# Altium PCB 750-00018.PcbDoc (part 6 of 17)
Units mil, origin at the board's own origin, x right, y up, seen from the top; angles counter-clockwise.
Board outline 7086.64 x 6299.21 mil, 8 copper layers (Top Layer, L2, L3, L4, L5, L6, L7, Bottom Layer), stack 60.6 mil thick; 1356 components, 1054 nets, 4851 pads, 4296 vias.
Unrouted connection lines stored in the file: 12.
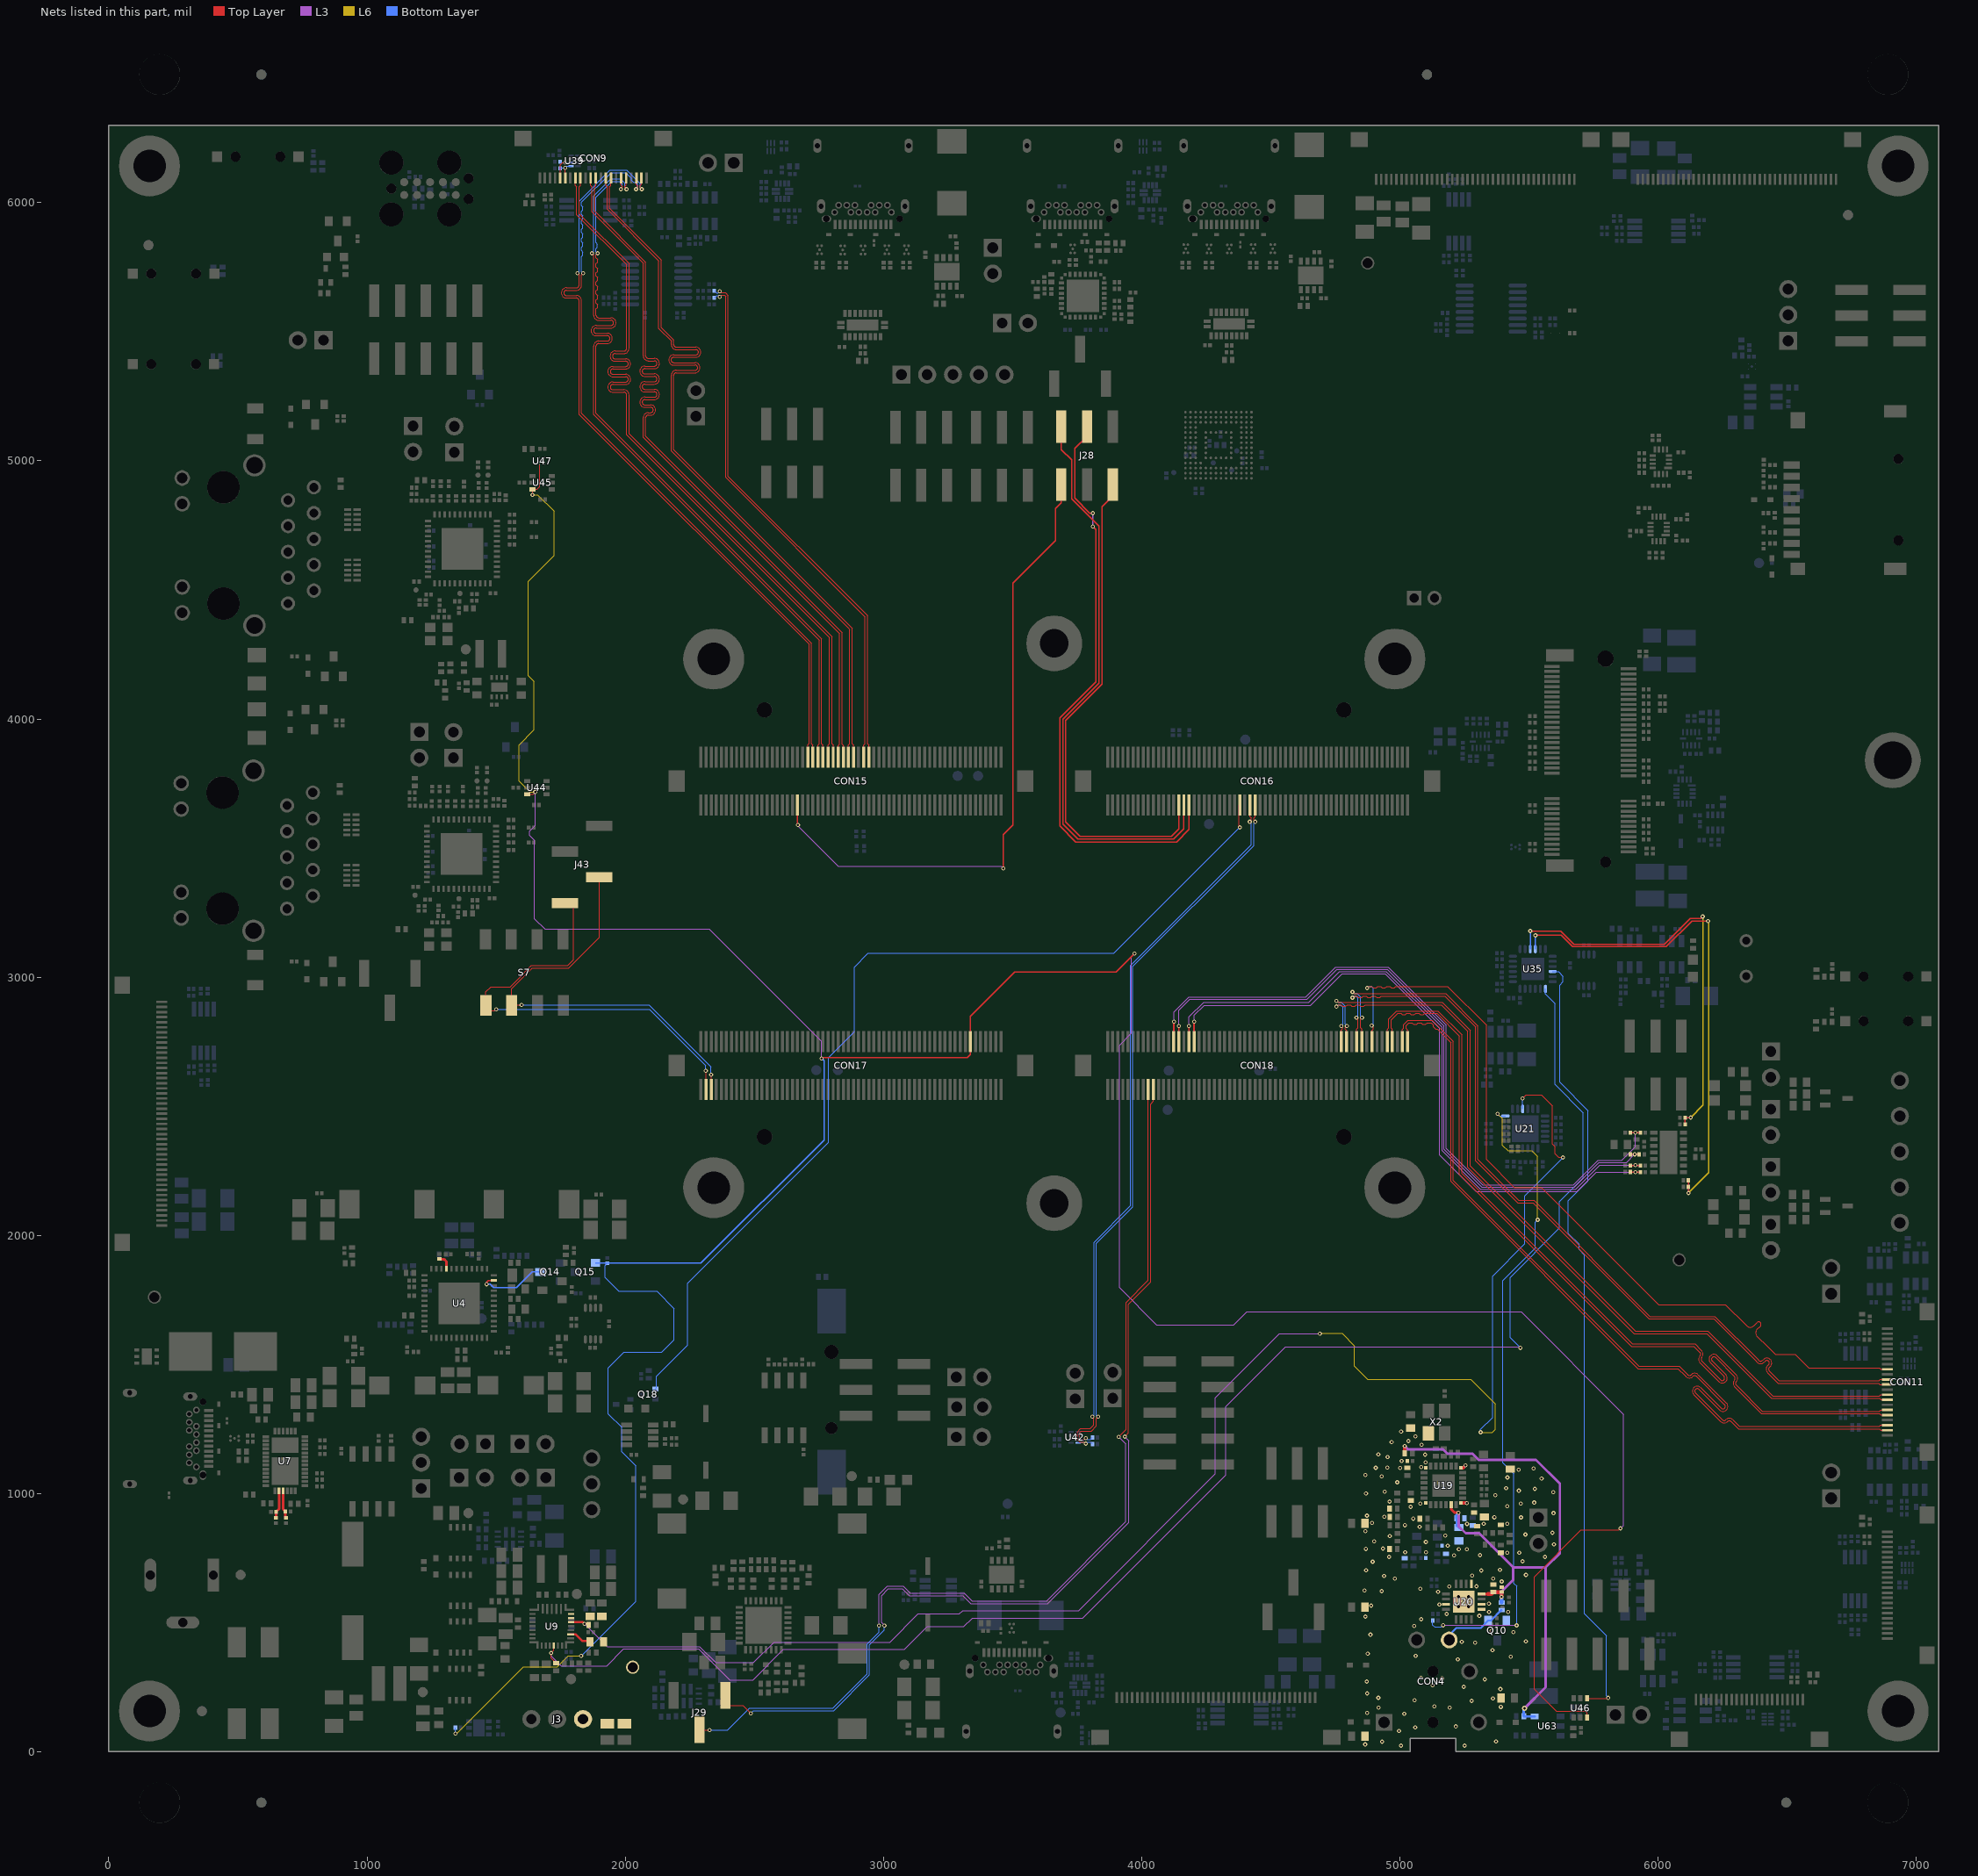
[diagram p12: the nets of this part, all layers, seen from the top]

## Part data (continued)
R346: library part CMP-RES-514-00100-1.13, "RES, SMT, 0402, Thick Film, 22.1k, 1%, 0.0625W", Alt. Manufacturer=Any, Manufacturer=Yageo, Manufacturer Part Number=RC0402FR-0722K1L, Operating Temperature=-55C~155C, Power=0.0625W, TOLERANCE=1%
R408 R531: library part CMP-RES-514-00153-1.11, "RES, SMT, 0402, Thick Film, 1.2k, 1%, 0.0625W", Alt. Manufacturer=Any, Manufacturer=Yageo, Manufacturer Part Number=RC0402FR-071K2L, Operating Temperature=-55C~155C, Power=0.0625W, TOLERANCE=1%
R413 R414 R536: library part CMP-RES-514-00059-1.17, "RES, SMT, 0402, Thick Film, 1.0k, 5%, 0.0625W", Alt. Manufacturer=Any, Manufacturer=Yageo, Manufacturer Part Number=RC0402JR-071KL, Operating Temperature=-55C~125C, Power=0.0625W, TOLERANCE=5%
R524: library part CMP-RES-514-00371-1.1, "RES, SMT, 0201, Thick Film, 432k, 1%, 0.05W", Alt. Manufacturer=Any, Manufacturer=Yageo, Manufacturer Part Number=RC0201FR-07432KL, Operating Temperature=-55C~125C, Power=0.05W, TOLERANCE=1%
R525 R599: library part CMP-RES-514-00226-1.9, "RES, SMT, 0402, Thick Film, 4.87k, 1%, 0.0625W", Alt. Manufacturer=Any, Manufacturer=Yageo, Manufacturer Part Number=RC0402FR-074K87L, Operating Temperature=-55C~155C, Power=0.0625W, TOLERANCE=1%
R568 R569: library part CMP-RES-514-00342-1.1, "RES, SMT, 0201, Thick Film, 5.1k, 1%, 0.05W", Alt. Manufacturer=Any, Manufacturer=Yageo, Manufacturer Part Number=RC0201FR-075K1L, Operating Temperature=-55C~125C, Power=0.05W, TOLERANCE=1%
R572: library part CMP-RES-514-00087-1.14, "RES, SMT, 0402, Thick Film, 220k, 1%, 0.0625W", Alt. Manufacturer=Any, Manufacturer=Yageo, Manufacturer Part Number=RC0402FR-07220KL, Operating Temperature=-55C~155C, Power=0.0625W, TOLERANCE=1%
R602: library part CMP-RES-514-00067-1.14, "RES, SMT, 0402, Thick Film, 3.0k, 5%, 0.0625W", Alt. Manufacturer=Any, Manufacturer=Yageo, Manufacturer Part Number=RC0402JR-073K0L, Operating Temperature=-55C~125C, Power=0.0625W, TOLERANCE=5%
R603 R605: library part CMP-RES-514-00187-1.4, "RES, SMT, 0603, Thick Film, 10k, 5%, 0.1W", Alt. Manufacturer=Any, Manufacturer=Yageo, Manufacturer Part Number=RC0603JR-0710KL, Operating Temperature=-55C~155C, Power=0.1W, TOLERANCE=5%
R604: library part CMP-RES-514-00212-1.8, "RES, SMT, 0402, Thick Film, 8.2k, 5%, 0.0625W", Alt. Manufacturer=Any, Manufacturer=Yageo, Manufacturer Part Number=RC0402JR-078K2L, Operating Temperature=-55C~155C, Power=0.0625W, TOLERANCE=5%
S1: library part CMP-SW-516-00023-1.3, "SW, TH, Custom, Slide, SPDT, ON_ON, 125VDC, 3A", Current Rating=3A, Manufacturer=E-Switch, Manufacturer Part Number=500ASSP1M2QE, Operating Temperature=-30C~85C, Voltage Rating AC/DC=125VDC
S2 S3 S5 S6 S8: library part CMP-SW-516-00024-1.3, "SW, SMT, Tact, SPST, Off-Mom", Manufacturer=EW-Switch, Manufacturer Part Number=BTS-1101NE-2-BB-RP-K
S7: library part CMP-SW-516-00021-1.5, "SW, SMT, DIP Switches, SPST, 100mA @ 50VDC / 25mA @ 24VDC", Current Rating="100mA @ 50VDC / 25mA @ 24VDC", Manufacturer=Diptronics, Manufacturer Part Number=DJR-04-T-V, Operating Temperature=-20C~85C
SB1 SB2 SB4 SB5 SB6: library part CMP-Misc-522-00004-1.18, "MSC, Solderbridge Closed"
SB3: library part CMP-Misc-522-00003-1.13, "MSC, Solderbridge Open"
TP1 TP2 TP3 TP4 TP5 TP6 TP7 TP8 TP10 TP11 TP12 TP13 TP14 TP15 TP16 TP17 TP20 TP21 TP22 TP23 TP24 TP25 TP26 TP29 TP30 TP31 TP33 TP34 TP35 TP36 TP37 TP38 TP39 TP40: library part CMP-MSC-522-00016-1.13, "MSC, Test Point"
TP9: library part CMP-MSC-522-00045-1.4, "MSC, Through-hole test pad for 1mm test hook block (red)", Manufacturer=TOBY, Manufacturer Part Number=TP-105-01-02
TP41 TP42 TP43: library part CMP-MSC-522-00046-1.4, "MSC, Through-hole test pad for 1mm test hook block (green)", Manufacturer=TOBY, Manufacturer Part Number=TP-105-01-05
U1: library part CMP-IC-510-00166-1.1, "IC, SMT, VQFN32, 4.5- to 18-V Input Voltage, 3-A/2-A/2-A Output Current Triple Synchronous Step-Down Converter With I2C Controlled Dynamic Voltage Scaling", Manufacturer="Texas Instruments", Manufacturer Part Number=TPS65263RHBR, Operating Temperature=-40C~125C, Supply Current=3A, Supply Voltage=4.5V~18V
U2 U3: library part CMP-IC-510-00374-1.0, "IC, SMT, SOT23-8, PMIC, 6-Bit, 1.7V~5.5V", Manufacturer="Texas Instruments", Manufacturer Part Number=INA232AIDDFR, Operating Temperature=-40C~125C, Supply Current="300 μA", Supply Voltage=1.7V~5.5V
U4: library part CMP-IC-510-00383-1.0, "IC, SMT, VQFN48, Switching Voltage Regulators, 4.5V~18V", Manufacturer=TI, Manufacturer Part Number=TPS65400QRGZTQ1, Operating Temperature=-40C~125C, Supply Voltage=4.5V~18V
U5 U6 U62: library part CMP-IC-510-00534-1.0, "IC, SMT, X2SON, Low-Power Single Bus Buffer Gate With 3-State Output, 0.8V~3.6V", Manufacturer=TI, Manufacturer Part Number=SN74AUP1G125DSFR, Operating Temperature="-40°C ~ 85°C", Supply Current="0.9 uA", Supply Voltage="0.8V ~ 3.6V"
U7: library part CMP-IC-510-00373-1.0, "IC, SMT, WQFN40, USB PD Controller, 5V~20V", Manufacturer="Texas Instruments", Manufacturer Part Number=TPS25751DREFR, Operating Temperature=-40C~125C, Supply Current=3A~5A, Supply Voltage=5V~20V
U8: library part CMP-IC-510-00403-1.0, "IC, SMT, SOIC8, EEPROM, I2C, 512Kb, 1MHz, 1.8V~5.5V, -40C~85C", Manufacturer="ON Semi", Manufacturer Part Number=CAT24C512WI-GT3, Operating Temperature=-40C~85C, Supply Voltage=1.8V~5.5V
U9: library part CMP-IC-510-00160-1.2, "IC, SMT, VQFN29, I2C controlled, 5-A, 1-4 cell buck-boost charger with dual-input selector and USB PD 3.0 OTG output", Manufacturer="Texas Instruments", Manufacturer Part Number=BQ25792RQM#, Operating Temperature=-40C~85C, Supply Current=5A, Supply Voltage=3.6V~24V
U10 U11: library part CMP-IC-510-00139-1.3, "IC, SMT, VQFN48, Ethernet PHYs, 1V, 1.8V, 2.5V", Manufacturer=TI, Manufacturer Part Number=DP83867IRRGZ, Operating Temperature=-40C~85C, Supply Voltage="1V, 1.8V, 2.5V"
U12 U15 U18: library part CMP-IC-510-00376-1.0, "IC, SMT, VSON8, USB Power Switch, 0.5A~5A, 2.5V~6.5V", Manufacturer="Texas Instruments", Manufacturer Part Number=TPS2557DRBT, Operating Temperature=-40C~125C, Supply Current=0.5A~5A, Supply Voltage=2.5V~6.5V
U13 U16 U51: library part CMP-IC-510-00372-1.0, "IC, SMT, X2QFN12, USB Controllers, 4.5V~5.5V", Manufacturer="Texas Instruments", Manufacturer Part Number=TUSB321RWBR, Operating Temperature=0C~70C, Supply Current="100 uA", Supply Voltage=4.5V~5.5V
U14 U17: library part CMP-IC-510-00375-1.0, "IC, SMT, VQFN20, Switch, SPDT, USB 3.1, 3V~3.6V", Manufacturer="Texas Instruments", Manufacturer Part Number=HD3SS3212IRKST, Operating Temperature=-40C~85C, Supply Current="800 uA", Supply Voltage=3V~3.6V
U19: library part CMP-IC-510-00377-1.5, "IC, SMT, VQFN28, Audio CODEC, 1.8V or 3.3V", Manufacturer="Texas Instruments", Manufacturer Part Number=TAC5112IRGER, Operating Temperature=-40C~125C, Supply Voltage="1.8V or 3.3V"
U20: library part CMP-IC-510-00187-1.3, "IC, SMT, VQFN16, Autonomous Audio Accessory Detection and Configuration Switch, 2.5V ~ 4.5V", Manufacturer="Texas Instruments", Manufacturer Part Number=TS3A227ERVAR, Operating Temperature=-40C~85C, Supply Voltage=2.5V~4.5V
U21: library part CMP-IC-510-00544-1.0, "IC, SMT, VQFN24, Interface I2C, 16-bit I/O Expander, 1.8V~5.5V, 25mA", Manufacturer=Microchip, Manufacturer Part Number=MCP23018-E/MJ, Operating Temperature=-40C~125C, Supply Current="25 mA", Supply Voltage=1.8V~5.5V
U22 U34: library part CMP-IC-510-00399-1.0, "IC, SMT, TSSOP-16, I2C/SMBus Switch with Reset & Voltage Translation, 1.65V~5.5V", Manufacturer=TI, Manufacturer Part Number=TCA9546APWR, Operating Temperature=-40C~85C, Supply Voltage=1.65V~5.5V
U23 U24: library part CMP-IC-510-00313-1.3, "IC, SMT, UQFN12, 4-Bit Bidirectional Multi-Voltage Level Translator for Open-Drain & Push- Pull, 0.8V~5V", Manufacturer="Texas Instruments", Manufacturer Part Number=LSF0204RUTR, Operating Temperature=-40C~125C, Supply Current="3.5 uA", Supply Voltage=0.8V~5V
U25: library part CMP-IC-510-00354-1.0, "IC, SMT, SOT8, 1.6V~5.5V, 40mΩ, 2.5A, low-IQ, Priority Power Multiplexer", Manufacturer=TI, Manufacturer Part Number=TPS2116DRLR, Operating Temperature=-40C~105C, Supply Current=2.5A, Supply Voltage=1.6V~5.5V
U26 U33 U38 U54 U64 U65 U66 U67 U68 U69 U70 U71: library part CMP-IC-510-00359-1.1, "IC, SMT, SOT-23-6, 5.5V, 2A, 52-mohm On-Resistance Load Switch", Manufacturer=TI, Manufacturer Part Number=TPS22918DBVR, Operating Temperature=-40C~105C, Supply Current=2A, Supply Voltage=1V~5.5V
U27: library part CMP-IC-510-00401-1.0, "IC, SMT, VSON14, CAN Interface, 4.5V~5.5V", Manufacturer="Texas Instruments", Manufacturer Part Number=TCAN1046AVDMTRQ1, Operating Temperature=-40C~150C, Supply Voltage=4.5V~5.5V
U28 U39 U40 U41 U42: library part CMP-IC-510-00205-1.5, "IC, SMT, QFN16_2.6x1.8, Bidirectional Level Translator, 1.2V~3.3V, 64mA", Manufacturer="Texas Instruments", Manufacturer Part Number=LSF0102DQER, Operating Temperature=-40C~85C, Supply Current=64mA, Supply Voltage=1.2V~3.3V
U29: library part CMP-IC-510-00318-1.1, "IC, SMT, QFN32, USB Interface IC USB to Serial UART Enhanced IC, 1.8V~5.25V, 15mA", Manufacturer=FTDI, Manufacturer Part Number=FT232RNQ, Operating Temperature=-40C~85C, Supply Current=15mA, Supply Voltage=1.8V~5.25V
U30: library part CMP-IC-510-00393-1.0, "IC, SMT, VQFN-HR(9), Switching Voltage Regulators", Manufacturer="Texas Instruments", Manufacturer Part Number=TPS62902RPJR, Operating Temperature=-40C~150C
U31 U52 U56 U57 U58 U59 U60 U61: library part CMP-IC-510-00398-1.0, "IC, SMT, VSSOP8, Level-Translating FM+ I2C Bus Repeater, 0.8V~5.5V", Manufacturer="Texas Instruments", Manufacturer Part Number=TCA9617BDGKR, Operating Temperature=-40C~85C, Supply Voltage=0.8V~5.5V
U32 U43: library part CMP-IC-510-00156-1.1, "IC, SMT, UQFN16, Low-Capacitance, 2:1 (SPDT) 4-Channel, Powered-Off Protected Switch with 1.8 V Logic", Manufacturer=TI, Manufacturer Part Number=TMUX1574RSVR, Operating Temperature=-40C~125C, Supply Current="68 uA", Supply Voltage=1.5V~5.5V
U35: library part CMP-IC-510-00384-1.0, "IC, SMT, WQFN24, Interface ICs, 16-bit I/O Expander, 1.08V~3.6V, 10uA", Manufacturer="Texas Instruments", Manufacturer Part Number=TCAL9539RTWR, Operating Temperature=-40C~125C, Supply Current="1 uA", Supply Voltage=1.08V~3.6V
U36: library part CMP-IC-510-00007-1.11, "IC, SMT, WSON8 (2.1x2.1) Exposed Pad, 2.9V~5.5V, 2A, 3MHz", Manufacturer="Texas Instruments", Manufacturer Part Number=TLV62065DSGR, Operating Temperature=-40C~85C, Supply Current=2A, Supply Voltage=3.3V~5V
U37 U47: library part CMP-IC-510-00502-1.12, "IC, SMT, 4X2SON, AND Gate, -40°C ~ 125°C, NA, ,", Manufacturer=TI, Manufacturer Part Number=SN74LVC1G08DPWR, Operating Temperature="-40°C ~ 125°C", Supply Current=NA, Supply Voltage="1.65V ~ 5.5V"
U44 U45 U46: library part CMP-IC-510-00495-1.0, "IC, SMT, SC70-6, 1-ch, 3-input 1.65V to 5.5V 32mA drive strength AND gate", Manufacturer="Texas Instruments", Manufacturer Part Number=SN74LVC1G11DCKR, Operating Temperature=-40C~125C, Supply Voltage=1.65V~5.5V
U48: library part CMP-IC-510-00499-1.0, "IC, SMT, WSON6, 79-mΩ On-Resistance Load Switch With Thermal Protection, 2.7V~18V, 3A", Manufacturer="Texas Instruments", Manufacturer Part Number=TPS22810DRVR, Operating Temperature=-40C~105C, Supply Current=3A, Supply Voltage=2.7V~18V
U49: library part CMP-IC-510-00185-1.3, "IC, SMT, TFBGA153, 8GB, Industrial iNAND 7250, with eMCC 5.1 interface", Capacity=8GB, Manufacturer="Western Digital", Manufacturer Part Number=SDINBDG4-8G-XI2, Operating Temperature=-40C~85C, Supply Current=NA, Supply Voltage=1.7V~3.6V
U50 U55: library part CMP-IC-510-00264-1.1, "IC, SMT, VSSOP8, Level Translator, Bidirectional, 2-Bit,  SMT, 1.65V~5.5V, 1A, VFSOP8, 2mm x 2.3mm", Manufacturer="Texas Instruments", Manufacturer Part Number=TXS0102DCU, Operating Temperature=-40C~85C, Supply Current=10uA, Supply Voltage=1.65V~5.5V
U53: library part CMP-IC-510-00192-1.2, "IC, SMT, SOIC8, EEPROM, I2C, 256Kb, 1MHz, 1.7V~5.5V, -40C~85C", Manufacturer=Giantec, Manufacturer Part Number=GT24C256C-2GLI-TR, Operating Temperature=-40C~85C, Supply Voltage=1.7V~5.5V
U63: library part CMP-IC-510-00001-1.7, "IC, SMT, SOT23-5, Fixed Linear, 3.3V 250mA,", Manufacturer="Texas Instruments", Manufacturer Part Number=TPS73433TDDCRQ1, Operating Temperature=-40C~105C, Supply Current=250mA, Supply Voltage=3.3V
U72 U73: library part CMP-IC-510-00213-1.6, "IC, SMT, VQFN-HR(12), 2.7-V to 22-V, 56-mΩ, 4.5-A, power mux with seamless switchover", Current Limit=4.5A, Manufacturer="Texas Instruments", Manufacturer Part Number=TPS2121RUXR, Operating Temperature=-40C~125C, Supply Voltage=2.8V~22V
U74: library part CMP-IC-510-00070-1.1, "IC, SMT, UQFN16, Data / Audio Low-Voltage dual DPDT analog switch, 1.65~4.45V, -40C~85C", Manufacturer="ON Semi", Manufacturer Part Number=FSA2466UMX, Operating Temperature=-40C~85C, Supply Voltage=1.65V~4.45V
X1: library part CMP-OSC-523-00004-1.2, "OSC, SMT, 4 pin 1.65mm x 2.05mm, TCXO, 0.032768 MHz, 30ppm, 1.8V~5V", Frequency="0.032768 MHz", Load (Capacitance)=15pF, Manufacturer=Siward, Manufacturer Part Number=OSCA23300-SCO-G646, Operating Temperature=-40C~85C, Supply Voltage=1.8V~5V, TOLERANCE="30 ppm"
X2: library part CMP-OSC-523-00013-1.1, "OSC, SMT, 4 pin 3.2mm x 2.5mm, OCXO, 12.288MHz, 25ppm, 1.71V~1.89V, 2.5mA", Frequency=12.288MHz, Manufacturer=Siward, Manufacturer Part Number=OSC813250-SCO-B192, Operating Temperature=-20C~70C, Supply Current=2.5mA, Supply Voltage=1.71V~1.89V, TOLERANCE=25ppm
Y1 Y2: library part CMP-XTL-524-00019-1.2, "XTL, SMT, 4 pin, 2.5mm x 2.0mm, 25MHz, 15ppm, 35 Ohm, 18pF", Frequency=25MHz, Load Capacitance=18pF, Manufacturer=Siward, Manufacturer Part Number=XTL581200-P120-165, Operating Temperature=-40C~105C, TOLERANCE=15ppm

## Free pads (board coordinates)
  round 39.37 smd paste-3937.01 mask+10: 0(153.48,5835.32) 0(360.48,157.48) 0(6735.52,5952.12)
  round 39.37 smd far side paste-3937.01 mask+10: 0(153.48,5835.32) 0(360.48,157.48) 0(6735.52,5952.12)
  round 157.48 hole 157.48 unplated mask+4: 0(196.85,6496.06) 0(196.85,-196.85) 0(6889.78,6496.06) 0(6889.79,-196.85)
  round 39.37 smd paste-3937.01 mask+4: 0(590.55,6496.06) 0(590.55,-196.85) 0(5104.99,6496.06) 0(6496.08,-196.85)
  round 39.37 smd far side paste-3937.01 mask+4: 0(590.55,6496.06) 0(590.55,-196.85) 0(5104.99,6496.06) 0(6496.08,-196.85)

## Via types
v1: diameter 16, hole 8, Top Layer to Bottom Layer, tented both sides, 3994 vias
v2: diameter 20, hole 10, Top Layer to Bottom Layer, tented both sides, 266 vias
v3: diameter 14, hole 7.87, Top Layer to Bottom Layer, tented both sides, 24 vias
v4: diameter 22, hole 12, Top Layer to Bottom Layer, tented both sides, 8 vias
v5: diameter 24, hole 12, Top Layer to Bottom Layer, tented both sides, 4 vias

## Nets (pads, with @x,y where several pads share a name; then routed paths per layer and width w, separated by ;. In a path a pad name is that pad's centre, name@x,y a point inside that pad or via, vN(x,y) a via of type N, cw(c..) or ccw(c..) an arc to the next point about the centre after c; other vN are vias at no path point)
ACD_nINT: R195.1 U21.24 | length 2561.6
  L3 w4: v1(5167.6,489.82) 5449.48,489.82 5451,488.3 v1(5452.13,489.43)
  L6 w4: v1(5378.6,2470.8) 5397.55,2451.85 5397.55,2349.32 5418.88,2327.99 5510.77,2327.99 5533.5,2305.26 v1(5533.5,2060.41)
  Bottom Layer w4: R195.1@5127.31,508.39 5127.31,490.06 5134.51,482.86 5160.65,482.86 v1(5167.6,489.82) ; v1(5378.6,2470.8) 5378.6,2469.24 5385.45,2462.38 U21.24@5408.49,2462.38 ; v1(5452.13,489.43) 5452.13,641.79 5441.65,652.28 5441.65,1076.64 5398.88,1119.41 5398.88,1825.23 5523.58,1949.94 5523.58,2050.49 v1(5533.5,2060.41)
ACS_DET: CON4.5 Q10.1 R188.1 | length 261.6
  Bottom Layer w8: CON4.5@5190.86,433.07 5190.86,451.97 5218.48,479.58 5313.4,479.58 Q10.1@5342,508.18 5352.38,508.18 5392.86,548.65 R188.1@5393.56,548.65
ADC_0: CON18.101 J29.1 | length 3859.7
  Top Layer w4: J29.1@2388.19,224.7 2388.19,188.02 2397.12,179.09 2455.33,179.09 v1(2486.01,148.41) ; v1(3934.4,1220.33) 3948.43,1234.35 3948.43,1733.8 4034.82,1820.19 4034.82,2508.94 4045.28,2519.39 CON18.101@4045.28,2565.4
  L3 w4: v1(3003.72,489.15) 2992.58,500.3 2992.58,604.41 3019.25,631.09 3072.42,631.09 3099.37,604.14 3308.08,604.14 3338.22,574 3636.04,574 3950.1,888.06 3950.1,1204.63 v1(3934.4,1220.33)
  Bottom Layer w4: v1(2486.01,148.41) 2496.71,159.11 2806.89,159.11 2945.58,297.8 2945.58,413.05 3003.72,471.19 v1(3003.72,489.15)
ADC_1: CON18.103 J29.2 | length 3919
  Top Layer w4: J29.2@2287.63,84.35 2326.29,84.35 v1(2326.92,83.71) ; v1(3910.86,1219.85) 3939.07,1248.06 3939.07,1739.7 4025.59,1826.22 CON18.103@4025.59,2565.4
  L3 w4: v1(2982.59,488.45) 2982.59,608.55 3015.12,641.08 3076.56,641.08 3103.51,614.13 3312.21,614.13 3342.35,583.99 3631.9,583.99 3938.74,890.83 3938.74,1191.98 v1(3910.86,1219.85)
  Bottom Layer w4: v1(2326.92,83.71) 2396.78,83.71 2481.93,168.87 2803.48,168.87 2936.27,301.66 2936.27,416.91 2981.94,462.58 v1@2981.94,488.45
ADCIN1: R60.1 R62.1 U7.2 | length 110.1
  Top Layer w10: R60.1@647.27,905.57 647.92,906.22 R62.1@647.92,929.47 659.23,940.78 U7.2@659.23,1010.71
ADCIN2: R59.1 R61.1 U7.3 | length 108.6
  Top Layer w10: U7.3@674.98,1010.71 674.98,939.52 R61.1@683.82,930.68 683.82,908.69 R59.1@685.88,906.63
AGND: C192.1 C193.2 C194.2 C195.1 C196.2 C197.2 C198.2 C201.2 C204.1 C208.2 C209.2 C211.2 C214.2 C276.2 C303.2 Q10.2 R50.1 R144.1 R177.2 R178.2 R179.2 R180.2 R181.2 R182.2 R187.2 R191.1 R205.2 R347.1 U19.A1 U19.A2 U19.A3 U19.A4 U20.1 U20.2 U20.5 U20.11 U20.17 X2.2 | length 44.8
  Top Layer w12: U19.A1@5236.6,963.83 5258,963.83 v1(5259.21,962.62) ; U19.A2@5236.6,1099.65 5245.07,1099.65 v1@5254.41,1108.99
  other v1: 5003.78,23.95 5250.99,23.74 4865.45,28.57 4930.59,39.22 5372.16,39.44 4996.43,80.37 5059.42,94.06 5216.73,98.19 5017,146.62 4873.39,150.73 4917.8,170.63 5193.13,170.37 5390.88,173.59 5133.11,175.61 5277.47,196.98 5057.25,199.98 5360.45,206.95 4916.53,208.94 4873.68,226.05 5389.28,242.71 5246.95,251.36 5126.69,257.01 4871.44,271.84 5328.73,280.28 5162.95,283.87 5081.19,286.12 5224.31,357.82 5429.39,367.97 5061.03,371.3 4875.42,379.46 5358.55,393.84 5291.31,421.99 5239.79,425.58 5487.61,427.44 4886.01,453.53 5439.8,463.39 5354.37,467.89 5054.86,486.63 5082.58,513.4 4866.27,523.72 5307.36,526.63 5181.32,533.82 5345.18,541.11 5418.97,541.25 4888.75,566.04 5153.01,570.07 5344.62,573.33 5147.86,619.74 4929.02,622.3 4862.69,624.37 5079.21,631.55 5191.44,639.64 5296.94,640.76 5394.43,659.79 4980.49,670.84 5361.25,670.99 4938.51,680.99 5279.87,682.01 5488.02,685.16 4868.86,702.97 5314.91,702.12 5387.42,704.39 4894.69,736.07 5475.5,737.67 4958.3,754.58 5561.91,754.74 5209.38,760.92 5309.68,761.68 5415.17,770.85 5462.08,771.24 5020.41,772.78 5100.62,773.02 5227.96,784.99 5259.1,784.55 4868.45,785.68 4934.49,787.18 5185.06,798.48 5596.68,802.83 5100.45,812.7 4900.02,815.42 4960.99,835.86 5175.38,836.87 5485.85,841.39 5590.7,848.28 4866.57,854.38 5076.54,871.21 5019.51,877.4 5260.04,882.57 5324.74,883.38 5415.81,883.31 4891.69,886.9 5052.15,902.94 5365.61,908.06 5469.22,907.75 4939.84,910 4872.11,914.8 5595.09,924.43 5041.09,948.39 5415.29,950.89 5078.67,961.62 5467.78,961.32 5519.91,965.27 4959.72,969.16 5369.62,994.04 4868.62,1000.26 5594.42,1005.07 4941.35,1006.99 5460.58,1011.17 5522.91,1018.45 5411.11,1020.7 4989.88,1043.63 5548.61,1058.02 5416.5,1062.37 4929.76,1067.04 4866.63,1071.58 5460.03,1092.38 5517.98,1097.08 5001.15,1098.91 4906.22,1100.05 4951.66,1101.04 5081.88,1101.97 5254.41,1109.08 5099.74,1120.91 5006.45,1126.61 4952.38,1141.77 5097.79,1150.78 4916.72,1152.02 5083.5,1188.94 4967.88,1199.48 5033.09,1203.48 5060.54,1221.79 5004.69,1240.43
  other v5: 5227.32,561.65 5266.69,561.65 5227.32,601.02 5266.69,601.02
AUD_3V3: C192.2 C193.1 C197.1 C198.1 C207.2 R188.2 R346.2 U19.23 U20.4 U63.5 | length 2512.9
  Top Layer w10: U19.23@5198.22,956.94 5198.22,940.24 5212.51,925.95 v1(5227.02,925.95) ; U20.4@5315.9,610.87 5340.72,610.87
  Top Layer w12: v1(5018.4,1183.66) 5018.47,1183.6 R346.2@5018.47,1156.55
  Top Layer w15: 5340.72,610.87 5354.17,610.87 C197.1@5361.65,618.35 C198.1@5392.28,618.35 ; v1(5393.24,599.89) 5394.18,600.83 C198.1@5394.18,618.14
  L3 w10: v1(5018.4,1183.66) 5031.32,1170.75 5168.3,1170.75 5185.41,1153.64 5281.85,1153.64 5304.82,1130.68 5527.11,1130.68 5619.58,1038.21 5619.58,768.98 5564.34,713.75 ; v1(5227.02,925.95) 5227.02,874.09 5254.56,846.55 5306.32,846.55 5439.12,713.75 ; v1(5393.24,599.89) 5393.24,620.38 5439.12,666.26 5439.12,713.75 ; v2(5483.27,168.87) 5564.34,249.94 5564.34,505.38 5564.34,601.64 5564.34,713.75 ; 5439.12,713.75 5564.34,713.75
  Bottom Layer w10: v1(5227.02,925.95) 5219.68,918.62 5219.68,904.46 C193.1@5220.36,903.79 5220.36,876.21 C192.2@5228.02,868.55 ; v2(5483.27,168.87) 5479.75,165.34 C207.2@5479.75,137.9 5480.91,136.73 U63.5@5521.65,136.73
  Bottom Layer w15: v1(5393.24,599.89) 5393.56,599.57 R188.2@5393.56,578.18
AUD_PWR_EN: U35.10 U46.1 | length 3073
  Top Layer w4: U46.1@5724.47,207.02 5805.18,207.02 v1(5806.88,208.73)
  Bottom Layer w4: U35.10@5591.4,3022.03 5613.58,3022.03 5632.07,3003.53 5632.07,2983.1 5618.86,2969.88 5618.86,2593.5 5729.14,2483.21 5729.14,2211.43 5652.65,2134.93 5652.65,2006.89 5694.23,1965.3 5694.23,1944.93 5715.34,1923.82 5715.34,533.82 5799.1,450.06 5799.1,216.51 v1(5806.88,208.73)
BAT_SENSE-: C90.2 C91.2 C116.1 C117.1 J3.3 R73.2 TP9.1 U9.22 U9.23
BATP: R73.1 U9.18 | length 86.5
  Top Layer w8: U9.18@1788.9,455.06 1807.57,455.06 1834.03,428.6 R73.1@1864.43,428.6
BOOT_SEL0#: CON17.117 J43.1 S7.1 | length 1732.4
  Top Layer w4: S7.1@1460.12,2890.71 1460.12,2943.14 1479.58,2962.6 1554.13,2962.6 1636.89,3045.36 1776.72,3045.36 1799.48,3068.12 1799.48,3286.59 J43.1@1765.77,3286.59 ; S7.1@1460.19,2870.96 1495.89,2870.96 v1(1500.77,2875.84) ; v1(2311.84,2637.09) 2312.99,2635.93 CON17.117@2312.99,2565.4
  Bottom Layer w4: v1(1500.77,2875.84) 2093.39,2875.84 2311.84,2657.39 v1(2311.84,2637.09)
BOOT_SEL1#: CON17.115 J43.2 S7.2 | length 1686.2
  Top Layer w4: S7.2@1560.12,2890.71 1560.12,2954.65 1640.31,3034.84 1780.43,3034.84 1899.95,3154.36 1899.95,3349.11 1899.63,3349.43 J43.2@1899.63,3386.59 ; S7.2@1560.19,2870.96 1581.36,2892.13 v1(1598.34,2892.13) ; v1(2332.49,2621.75) 2332.68,2621.56 CON17.115@2332.68,2565.4
  Bottom Layer w4: v1(1598.34,2892.13) 2092.55,2892.13 2332.49,2652.19 v1(2332.49,2621.75)
CAM_A_MCK: CON15.40 J28.1 | length 2525.8
  Top Layer w5: CON15.40@2667.33,3666.88 2667.33,3590.86 v1(2668.79,3589.4) ; v1@3464.19,3421.03 3464.19,3552.4 3501.4,3589.62 3501.4,4526.3 3666.5,4691.4 3666.5,4815.96 3688.03,4837.49 J28.1@3688.03,4907.97
  L3 w4: v1(2668.79,3589.4) 2667.57,3588.18 2667.57,3586.38 2824.55,3429.41 3455.81,3429.41 v1(3463.82,3421.41)
"CAM_A_SCL / CSI_A_TX_P": CON15.67 R511.1 | length 2083.2
  Top Layer w4: v1(2365.51,5656.79) 2365.51,5653.72 2368.08,5651.16 2388,5651.16 2398.55,5640.6 2398.55,4939.38 2937.82,4400.1 2937.82,3903.42 2942.92,3898.33 CON15.67@2942.92,3851.92
  Bottom Layer w4: R511.1@2344.6,5658.2 2353.23,5649.58 2358.29,5649.58 v1(2365.51,5656.79)
"CAM_A_SDA / CSI_A_TX_N": CON15.65 R512.1 | length 2065.1
  Top Layer w4: v1@2365.54,5635.12 2372.08,5641.66 2384.06,5641.66 2389.05,5636.67 2389.05,4935.44 2928.32,4396.17 2928.32,3904.04 2923.23,3898.95 CON15.65@2923.23,3851.92
  Bottom Layer w4: R512.1@2344.6,5631.45 2353.23,5640.08 2360.41,5640.08 v1(2365.51,5634.98)
"CAM_B_MCK / PWM_3": CON16.30 J28.5 | length 1948.4
  Top Layer w5: J28.5@3888.03,4907.97 3888.03,4864.09 3846.14,4822.19 3846.14,4135.19 3705.79,3994.85 3705.79,3600.8 3761.25,3545.34 4115.31,3545.34 4143.7,3573.74 CON16.30@4143.7,3666.88
"CAM_B_SCL / CSI_B_TX_P": CON16.58 R523.1 U42.4 | length 2875.4
  Top Layer w4: v1(3783.19,1193.16) 3777.1,1199.25 3760.36,1199.25 3750.49,1209.11 3750.49,1238.78 3763.16,1251.45 3800.95,1251.45 3814.82,1265.32 3814.82,1292.03 v1(3809.21,1297.64) ; v1(4418.18,3602.02) 4424.38,3608.23 4424.38,3617.41 4419.29,3622.5 CON16.58@4419.29,3666.88
  Bottom Layer w4: U42.4@3753.47,1196.96 3760.19,1196.96 3762.33,1199.1 3777.25,1199.1 v1(3783.19,1193.16) 3789.8,1199.78 3801.42,1199.78 R523.1@3809.32,1191.89 ; v1(3809.21,1297.64) 3815.16,1303.59 3815.16,1335.61 3815.16,1973.65 3956.42,2114.91 3956.42,3045.6 4424.34,3513.52 4424.34,3595.86 v1(4418.18,3602.02)
"CAM_B_SDA / CSI_B _TX_N": CON16.60 R522.1 U42.3 | length 2859.5
  Top Layer w4: v1(3783.19,1214.66) 3777.28,1208.75 3764.29,1208.75 3759.99,1213.05 3759.99,1234.85 3767.09,1241.95 3804.89,1241.95 3824.32,1261.39 3824.32,1291.25 v1(3830.71,1297.64) ; CON16.60@4438.98,3666.88 4438.98,3622.01 4433.88,3616.92 4433.88,3608.14 v1(4440,3602.02)
  Bottom Layer w4: U42.3@3753.47,1210.74 3759.9,1210.74 3762.04,1208.6 3777.13,1208.6 v1(3783.19,1214.66) 3788.57,1209.28 3801.42,1209.28 R522.1@3809.32,1217.17 ; v1(3830.71,1297.64) 3824.66,1303.69 3824.66,1335.61 3824.66,1969.71 3965.92,2110.97 3965.92,3041.66 4433.84,3509.58 4433.84,3595.86 v1(4440,3602.02)
"CAM_C_MCK / PWM_4": CON16.32 J28.2 | length 2259.5
  Top Layer w5: J28.2@3688.03,5132.38 3688.03,5043.77 3728.64,5003.16 3728.64,4852.79 3834.48,4746.96 3834.48,4138.47 3695,3999 3695,3592.78 3753.07,3534.72 4123.93,3534.72 4163.39,3574.17 CON16.32@4163.39,3666.88
"CAM_D_MCK / PWM_5": CON16.34 J28.4 | length 2305
  Top Layer w5: J28.4@3788.03,5132.38 3788.03,5094.36 3741.44,5047.77 3741.44,4855.5 3799.53,4797.41 v1(3810.85,4797.41) ; v1(3810.94,4745.95) 3823.36,4733.54 3823.36,4144.11 3683.04,4003.79 3683.04,3585.45 3744.54,3523.95 4134.6,3523.95 4183.07,3572.42 CON16.34@4183.07,3666.88
  L3 w5: v1(3810.85,4797.41) 3810.85,4746.05 v1(3810.94,4745.95)
CAN_A_RX: CON18.92 R356.1 R358.2 | length 2669.3
  Top Layer w5: R356.1@5892.39,2313.8 5909.19,2313.8 v1(5909.32,2313.93) 5926.89,2313.93 R358.2@5927.02,2313.8
  Top Layer w6: CON18.92@4143.7,2750.44 v1@4143.7,2810.35
  L3 w4: v1(4143.89,2810.54) 4143.89,2872.66 4185.66,2914.44 4639.66,2914.44 4755.97,3030.75 4950.66,3030.75 5170.56,2810.84 5170.56,2333.55 5316.98,2187.12 5675.22,2187.12 5770.46,2282.36 5877.75,2282.36 v1(5909.32,2313.93)
CAN_A_STB: R279.1 R355.2 U35.3 | length 1649.7
  Top Layer w5: v1(5504.98,3178.75) 5622.73,3178.75 5674.15,3127.33 6024.09,3127.33 6124.5,3227.74 6165.45,3227.74 v1(6172.58,3234.88) ; R355.2@6104.62,2430.09 6104.62,2455.67 R279.1@6104.71,2455.67 6125.07,2455.67 v1(6125.76,2456.36)
  L6 w5: v1(6125.76,2456.36) 6174.16,2504.76 6174.16,3233.29 v1(6172.58,3234.88)
  Bottom Layer w5: U35.3@5504.55,3108.88 5504.98,3109.3 v1(5504.98,3178.75)
CAN_A_TX: CON18.94 R354.1 R357.2 | length 2757
  Top Layer w5: R354.1@5892.39,2397.49 5911.13,2397.49 v1(5911.65,2398.01) 5930.29,2398.01 R357.2@5930.82,2397.48
  Top Layer w6: CON18.94@4124.02,2750.44 v1@4124.02,2827.49
  L3 w4: v1(4124.88,2828.35) 4124.88,2865.53 4183.09,2923.75 4635.01,2923.75 4750.04,3038.78 4953.98,3038.78 5178.59,2814.17 5178.59,2336.87 5320.31,2195.16 5671.57,2195.16 5767.04,2290.62 5859.36,2290.62 5911.65,2342.91 v1(5911.65,2398.01)
CAN_B_MCU_RX: CON18.86 R361.2 R365.2 | length 2583.4
  Top Layer w5: R361.2@5892.39,2245.76 5893.15,2245 v1(5911.65,2245) 5930.46,2245 R365.2@5930.82,2245.35
  Top Layer w6: CON18.86@4202.76,2750.44 v1@4202.76,2827.49
  L3 w4: v1(4203.62,2828.35) 4203.62,2852.81 4242.48,2891.67 4653.81,2891.67 4775.95,3013.81 4943.12,3013.81 5152.45,2804.49 5152.45,2312.66 5294.62,2170.5 5686.11,2170.5 5760.61,2245 v1(5911.65,2245)
CAN_B_MCU_TX: CON18.88 R363.2 R364.2 | length 2603.5
  Top Layer w5: R363.2@5892.39,2270.85 5910.62,2270.85 v1(5911.65,2271.88) 5912.62,2270.91 R364.2@5930.82,2270.91
  Top Layer w6: CON18.88@4183.07,2750.44 v1@4183.07,2810.35
  L3 w4: v1(4183.26,2810.54) 4183.26,2846.09 4240.46,2903.29 4647.39,2903.29 4766.24,3022.14 4946.4,3022.14 5161.65,2806.9 5161.65,2329.28 5311.91,2179.02 5681.52,2179.02 5774.39,2271.88 v1(5911.65,2271.88)
CAN_B_STB: R286.1 R362.2 U35.4 | length 1918.1
  Top Layer w5: v1(5524.82,3162.06) 5624.1,3162.06 5668.26,3117.91 6031.46,3117.91 6131.53,3217.98 6192.91,3217.98 v1(6193.18,3217.71) ; R362.2@6117.28,2213.3 6117.28,2187.86 R286.1@6117.21,2187.79 6117.46,2187.55 v1(6117.46,2164.11)
  L6 w5: v1(6117.46,2164.11) 6195.77,2242.42 6195.77,3215.12 v1(6193.18,3217.71)
  Bottom Layer w5: U35.4@5524.23,3108.88 5524.23,3161.48 v1(5524.82,3162.06)
Carrier_Power_Enable: Q14.3 U4.23 | length 276.7
  Top Layer w5: v1(1463.26,1810.75) 1463.26,1818.52 1470.21,1825.47 U4.23@1490.54,1825.47
  Bottom Layer w5: v1(1463.26,1810.75) 1475.75,1810.75 1489.54,1796.96 1578.64,1796.96 1639.89,1858.21 Q14.3@1670.91,1858.21
CARRIER_PWR_EN: CON17.14 Q15.1 R161.2 R555.1 U44.6 U45.6 U46.6 U47.1 | length 13981.7
  Top Layer w4: U44.6@1619.67,3708.85 1642.32,3708.85 v1(1651.1,3717.63) ; v1(1640.71,4868) 1641.13,4868.42 U45.6@1641.13,4889.52 1658.03,4889.52 1668.85,4900.33 U47.1@1668.85,4983.83 ; U46.6@5724.47,132.02 5724.47,149.83 5717.54,156.76 5606.47,156.76 5520.51,242.73 5520.51,677.94 5701.17,858.61 5847.42,858.61 v1(5854.18,865.37)
  Top Layer w6: v1(2760.32,2684.83) 2764.22,2688.73 3324.46,2688.73 3336.62,2700.88 CON17.14@3336.62,2750.44 3336.62,2848.67 3507.94,3019.99 3900.66,3019.99 v1(3972.11,3091.44)
  L3 w4: v1(1651.1,3717.63) 1651.1,3587.12 1629.69,3565.7 1629.69,3548.79 1648.81,3529.67 1648.81,3225.71 1688.66,3185.85 2325.43,3185.85 2760.32,2750.96 v1(2760.32,2684.83) ; v1(3972.11,3091.44) 3960.9,3080.24 3960.9,2782.92 3913.64,2735.66 3913.64,1797.19 4057.15,1653.69 4356.98,1653.69 4406.82,1703.53 5469.31,1703.53 5865.71,1307.14 5865.71,876.9 v1(5854.18,865.37)
  L6 w4: v1(1342.56,70.68) 1347.37,70.68 1351.03,74.34 1605.46,328.77 1736.16,328.77 1778.32,370.94 v1(1828.94,370.94) ; v1(1640.71,4868) 1660.25,4868 1723.96,4804.29 1723.96,4633.15 1624.54,4533.74 1624.54,4166.92 1646.8,4144.66 1646.8,3957.93 1588.08,3899.21 1588.08,3759.64 1630.09,3717.63 v1(1651.1,3717.63)
  Bottom Layer w4: R555.1@1342.26,93.34 1342.26,70.98 v1(1342.56,70.68) ; v1@1829.91,371.18 2040.87,582.14 2040.87,1106.92 1985.99,1161.8 1985.99,1256.32 1933.53,1308.78 1933.53,1486.09 1994.8,1547.36 2141.35,1547.36 2189.08,1595.1 2189.08,1716.68 2122.38,1783.39 1974.36,1783.39 1921.61,1836.14 1921.61,1883.17 R161.2@1930.77,1892.33
  Bottom Layer w5: Q15.1@1884.74,1893.44 R161.2@1930.85,1893.44 ; R161.2@1930.77,1892.33 2292.85,1892.33 2769.42,2368.9 2769.42,2676.53 2761.13,2684.83 v1(2760.32,2684.83)
CARRIER_STBY#: CON16.54 Q18.1 | length 3760
  Top Layer w4: CON16.54@4379.92,3666.88 4376.89,3663.85 4376.89,3583.15 v1(4380.08,3579.96)
  Bottom Layer w4: Q18.1@2116.59,1404.85 2121.63,1409.89 2121.63,1454.27 2242.14,1574.77 2242.14,1814.98 2787.22,2360.06 2787.22,2688.33 2887.16,2788.27 2887.16,3039.36 2940.68,3092.88 3891.46,3092.88 4378.54,3579.96 v1(4380.08,3579.96)
CB4: R43.1 U4.33 | length 57.5
  Top Layer w10: R43.1@1281.68,1908.03 1297.91,1908.03 1307.47,1898.48 U4.33@1307.47,1870.74
CHGR_CEn: R67.1 U9.13 U35.13 | length 6214.8
  Top Layer w4: U9.13@1723.45,411.75 1723.45,392.99 v1(1712.68,382.22) 1712.68,362.96 R67.1@1732.57,343.08
  L3 w4: v1(1712.68,382.22) 1712.68,372.13 1752.25,332.56 1928.19,332.56 1994.14,398.51 2283.81,398.51 2404.09,278.23 2494.21,278.23 2612.42,396.45 3081.07,396.45 3169.53,484.91 3311.36,484.91 3344.46,518.01 3771.96,518.01 4325.5,1071.55 4325.5,1337.75 4556.16,1568.41 5461.93,1568.41 v1(5466.07,1564.26)
  Bottom Layer w4: v1(5466.07,1564.26) 5427.11,1603.23 5427.11,1836.58 5618.6,2028.07 5618.6,2131.02 5709.7,2222.12 5709.7,2474.94 5600.36,2584.28 5600.36,2897.7 5563.6,2934.46 U35.13@5563.6,2954.86
CHGR_INTn: R68.1 U9.21 U21.3 | length 6289.8
  Top Layer w4: v1(5474.77,2530.82) 5488.51,2544.56 5547.96,2544.56 5590.66,2501.86 5590.66,2353.86 5600.66,2343.87 5600.66,2315.56 5614.24,2301.98 v1(5631.32,2301.98)
  Top Layer w8: U9.21@1790.38,502.31 1835.2,502.31 v1(1842.13,495.38) 1853.79,495.38 R68.1@1858.36,490.8
  L3 w4: v1(1842.13,495.38) 1929.83,407.67 2288.24,407.67 2350.83,345.08 2497.11,345.08 2576.78,424.76 3024.59,424.76 3133.72,533.89 3293.88,533.89 3306.75,546.76 3756.34,546.76 4285.77,1076.19 4285.77,1371.43 4533.6,1619.26 v1(4690.13,1619.26)
  L6 w4: v1(4690.13,1619.26) 4691.58,1620.71 4775.47,1620.71 4824.61,1571.57 4824.61,1493.38 4875.14,1442.85 5275.09,1442.85 5370.22,1347.72 5370.22,1247.98 5358.31,1236.08 5314.06,1236.08 v1(5312.65,1237.49)
  Bottom Layer w4: v1(5312.65,1237.49) 5312.65,1248.1 5358.73,1294.19 5358.73,1842.37 5483.71,1967.35 5483.71,2153.04 5631.32,2300.65 v1(5631.32,2301.98) ; v1(5474.77,2530.82) 5475.42,2530.17 U21.3@5475.42,2489.95
CSI_A_CLOCK_N: CON9.8 CON15.61 | length 3020.5
  Top Layer w4: CON9.8@1944.59,6095.14 1944.59,6067.18 1939.49,6062.08 1939.49,5977.82 2139.69,5777.63 2139.69,5516.31 2187.33,5468.67 2187.33,5457.45 2187.33,5450.7 ccw(c2197.58,5450.7) 2197.58,5440.45 2273.02,5440.45 cw(c2273.02,5420.7) 2273.02,5400.95 2187.58,5400.95 ccw(c2187.58,5390.7) 2187.58,5380.45 2269.89,5380.45 cw(c2269.89,5360.7) 2269.89,5340.95 2197.58,5340.95 ccw(c2197.58,5330.7) 2187.33,5330.7 2187.33,5244.78 2187.33,5042.26 2240.82,4988.77 2878.77,4350.82 2878.77,3903.83 2883.86,3898.74 CON15.61@2883.86,3851.92
CSI_A_CLOCK_P: CON9.9 CON15.59 | length 3020.5
  Top Layer w4: CON9.9@1924.9,6095.14 1924.9,6067.16 1929.99,6062.07 1929.99,5973.88 2130.19,5773.69 2130.19,5512.37 2177.83,5464.73 2177.83,5457.45 2177.83,5450.7 ccw(c2197.58,5450.7) 2197.58,5430.95 2273.02,5430.95 cw(c2273.02,5420.7) 2273.02,5410.45 2187.58,5410.45 ccw(c2187.58,5390.7) 2187.58,5370.95 2269.89,5370.95 cw(c2269.89,5360.7) 2269.89,5350.45 2197.58,5350.45 ccw(c2197.58,5330.7) 2177.83,5330.7 2177.83,5244.78 2177.83,5038.33 2863.61,4352.54 2869.27,4346.88 2869.27,3904.02 2864.18,3898.92 CON15.59@2864.18,3851.92
CSI_A_DATA0_N: CON9.2 CON15.43 | length 3020.2
  Top Layer w4: v1(1814.8,5726.07) 1821.08,5719.8 1821.08,5705.66 1821.08,5680.28 cw(c1810.83,5680.28) 1810.83,5670.03 1772.25,5670.03 ccw(c1772.25,5650.28) 1772.25,5630.53 1810.83,5630.53 cw(c1810.83,5620.28) 1821.08,5620.28 1821.08,5613.53 1821.08,5179.78 2711.62,4289.24 2711.62,3905.08 2706.7,3900.16 CON15.43@2706.7,3851.92 ; CON9.2@2062.7,6095.14 2062.7,6070.81 2057.6,6065.72 2057.6,6058.16 v1(2063.77,6052)
  Bottom Layer w4: v1(1814.8,5726.07) 1820.96,5732.23 1820.96,6005 1941.19,6125.23 2005.69,6125.23 2057.43,6073.49 2057.43,6058.33 v1(2063.77,6052)
CSI_A_DATA0_P: CON9.3 CON15.45 | length 3020.5
  Top Layer w4: v1(1836.62,5726.07) 1830.58,5720.04 1830.58,5705.66 1830.58,5680.28 cw(c1810.83,5680.28) 1810.83,5660.53 1772.25,5660.53 ccw(c1772.25,5650.28) 1772.25,5640.03 1810.83,5640.03 cw(c1810.83,5620.28) 1830.58,5620.28 1830.58,5613.53 1830.58,5183.72 2721.12,4293.17 2721.12,3904.88 2726.38,3899.62 CON15.45@2726.38,3851.92 ; v1(2041.95,6052) 2048.1,6058.16 2048.1,6064 2043.01,6069.1 CON9.3@2043.01,6095.14
  Bottom Layer w4: v1(1836.62,5726.07) 1830.46,5732.23 1830.46,5791.06 1835.96,5796.56 1835.96,5808.56 1830.46,5814.06 1830.46,5826.06 1835.96,5831.56 1835.96,5843.56 1830.46,5849.06 1830.46,5861.06 1835.96,5866.56 1835.96,5878.56 1830.46,5884.06 1830.46,5896.06 1835.96,5901.56 1835.96,5913.56 1830.46,5919.06 1830.46,5931.06 1835.96,5936.56 1835.96,5948.56 1830.46,5954.06 1830.46,5966.06 1835.96,5971.56 1835.96,5983.56 1830.46,5989.06 1830.46,6001.06 1945.13,6115.73 2001.75,6115.73 2023.18,6094.3 2023.18,6086.52 2031.67,6078.04 2039.45,6078.04 2047.93,6069.56 2047.93,6057.98 v1(2041.95,6052)
CSI_A_DATA1_N: CON9.5 CON15.47 | length 3020.5
  Top Layer w4: v1(1870.89,5803.83) 1877.42,5797.3 1877.42,5570.88 1877.42,5564.13 ccw(c1897.17,5564.13) 1897.17,5544.38 1944.23,5544.38 cw(c1944.23,5534.13) 1944.23,5523.88 1887.17,5523.88 ccw(c1887.17,5504.13) 1887.17,5484.38 1930.25,5484.38 cw(c1930.25,5474.13) 1930.25,5463.88 1897.17,5463.88 ccw(c1897.17,5444.13) 1877.42,5444.13 1877.42,5380.64 1877.42,5179.43 2750.88,4305.97 2750.88,3904.05 2746.07,3899.24 CON15.47@2746.07,3851.92 ; CON9.5@2003.64,6095.14 2003.64,6068.34 1998.55,6063.25 1998.55,6058.16 v1(2004.71,6052)
  Bottom Layer w4: v1(1870.89,5803.83) 1877.04,5809.99 1877.04,6025.04 1944.05,6092.05 1981.28,6092.05 1997.71,6075.62 1997.71,6059 v1(2004.71,6052)
CSI_A_DATA1_P: CON9.6 CON15.49 | length 3020.2
  Top Layer w4: v1(1892.7,5803.83) 1886.92,5798.04 1886.91,5786.04 1892.41,5780.54 1892.42,5768.54 1886.92,5763.04 1886.91,5751.04 1892.41,5745.54 1892.42,5733.54 1886.92,5728.04 1886.91,5716.04 1892.41,5710.54 1892.42,5698.54 1886.92,5693.04 1886.91,5681.04 1892.41,5675.54 1892.42,5663.54 1886.92,5658.04 1886.91,5646.04 1892.41,5640.54 1892.42,5628.54 1886.92,5623.04 1886.91,5611.04 1892.41,5605.54 1892.42,5593.54 1886.92,5588.04 1886.92,5570.88 1886.92,5564.13 ccw(c1897.17,5564.13) 1897.17,5553.88 1944.23,5553.88 cw(c1944.23,5534.13) 1944.23,5514.38 1887.17,5514.38 ccw(c1887.17,5504.13) 1887.17,5493.88 1930.25,5493.88 cw(c1930.25,5474.13) 1930.25,5454.38 1897.17,5454.38 ccw(c1897.17,5444.13) 1886.92,5444.13 1886.92,5380.64 1886.92,5183.36 2760.38,4309.9 2760.38,3903.57 2765.75,3898.19 CON15.49@2765.75,3851.92 ; v1(1982.89,6052) 1989.05,6058.16 1989.05,6063.54 1983.96,6068.63 CON9.6@1983.96,6095.14
  Bottom Layer w4: v1(1892.7,5803.83) 1886.54,5809.99 1886.54,5821.99 1892.04,5827.49 1892.04,5839.49 1886.54,5844.99 1886.54,6021.11 1947.99,6082.55 1977.35,6082.55 1988.21,6071.69 1988.21,6057.32 v1(1982.89,6052)
CSI_A_DATA2_N: CON9.11 CON15.57 | length 3020.5
  Top Layer w4: CON9.11@1885.53,6095.14 1885.53,6066.77 1880.44,6061.68 1880.44,5967.66 2078.97,5769.13 2078.97,5473.65 2078.97,5406.9 ccw(c2089.22,5406.9) 2089.22,5396.65 2112.67,5396.65 cw(c2112.67,5376.9) 2112.67,5357.15 2075.8,5357.15 ccw(c2075.8,5346.9) 2075.8,5336.65 2112.67,5336.65 cw(c2112.67,5316.9) 2112.67,5297.15 2075.8,5297.15 ccw(c2075.8,5286.9) 2075.8,5276.65 2112.67,5276.65 cw(c2112.67,5256.9) 2112.67,5237.15 2075.8,5237.15 ccw(c2075.8,5226.9) 2075.8,5216.65 2098.03,5216.65 cw(c2098.03,5196.9) 2098.03,5177.15 2089.22,5177.15 ccw(c2089.22,5166.9) 2078.97,5166.9 2078.97,5134.9 2078.97,5094.94 2839.4,4334.51 2839.4,3902.93 2844.49,3897.84 CON15.57@2844.49,3851.92
CSI_A_DATA2_P: CON9.12 CON15.55 | length 3020.5
  Top Layer w4: CON9.12@1865.85,6095.14 1865.85,6067.33 1870.94,6062.24 1870.94,5963.72 2069.47,5765.19 2069.47,5473.65 2069.47,5406.9 ccw(c2089.22,5406.9) 2089.22,5387.15 2112.67,5387.15 cw(c2112.67,5376.9) 2112.67,5366.65 2075.8,5366.65 ccw(c2075.8,5346.9) 2075.8,5327.15 2112.67,5327.15 cw(c2112.67,5316.9) 2112.67,5306.65 2075.8,5306.65 ccw(c2075.8,5286.9) 2075.8,5267.15 2112.67,5267.15 cw(c2112.67,5256.9) 2112.67,5246.65 2075.8,5246.65 ccw(c2075.8,5226.9) 2075.8,5207.15 2098.03,5207.15 cw(c2098.03,5196.9) 2098.03,5186.65 2089.22,5186.65 ccw(c2089.22,5166.9) 2069.47,5166.9 2069.47,5134.9 2069.47,5091.01 2824.24,4336.23 2829.9,4330.58 2829.9,3903.1 2824.81,3898.01 CON15.55@2824.81,3851.92
CSI_A_DATA3_N: CON9.14 CON15.53 | length 3020.3
  Top Layer w4: CON9.14@1826.48,6095.14 1826.48,6066.6 1821.61,6061.74 1821.61,5956.67 2014.61,5763.68 2014.61,5472.17 2014.61,5435.44 cw(c1994.86,5435.44) 1994.86,5415.69 1960.71,5415.69 ccw(c1960.71,5405.44) 1960.71,5395.19 2001.27,5395.19 cw(c2001.27,5375.44) 2001.27,5355.69 1952.1,5355.69 ccw(c1952.1,5345.44) 1952.1,5335.19 2001.27,5335.19 cw(c2001.27,5315.44) 2001.27,5295.69 1952.1,5295.69 ccw(c1952.1,5285.44) 1952.1,5275.19 1994.86,5275.19 cw(c1994.86,5255.44) 2014.61,5255.44 2014.61,5248.69 2014.61,5105.1 2800.03,4319.68 2800.03,3903.74 2805.12,3898.65 CON15.53@2805.12,3851.92
CSI_A_DATA3_P: CON9.15 CON15.51 | length 3020.5
  Top Layer w4: CON9.15@1806.79,6095.14 1806.79,6066.8 1812.11,6061.48 1812.11,5952.74 2005.11,5759.74 2005.11,5472.17 2005.11,5435.44 cw(c1994.86,5435.44) 1994.86,5425.19 1960.71,5425.19 ccw(c1960.71,5405.44) 1960.71,5385.69 2001.27,5385.69 cw(c2001.27,5375.44) 2001.27,5365.19 1952.1,5365.19 ccw(c1952.1,5345.44) 1952.1,5325.69 2001.27,5325.69 cw(c2001.27,5315.44) 2001.27,5305.19 1952.1,5305.19 ccw(c1952.1,5285.44) 1952.1,5265.69 1994.86,5265.69 cw(c1994.86,5255.44) 2005.11,5255.44 2005.11,5248.69 2005.11,5101.16 2790.53,4315.75 2790.53,3903.54 2785.44,3898.44 CON15.51@2785.44,3851.92
"CSI_A_GPIO0 / PWR": CON9.17 R374.1 U39.5 | length 86
  Top Layer w4: v1(1767.13,6134.05) 1767.13,6095.44 CON9.17@1767.42,6095.14
  Bottom Layer w4: R374.1@1746.98,6132.41 1748.62,6134.05 v1(1767.13,6134.05) 1774.17,6141.1 U39.5@1790.38,6141.1
"CSI_A_GPIO1 / RST": CON9.18 R373.1 U39.6 | length 118.6
  Top Layer w4: CON9.18@1747.74,6095.14 1747.74,6145.64 1756.68,6154.58 v1(1767.28,6154.58)
  Bottom Layer w4: R373.1@1746.98,6157.88 1750.28,6154.58 v1(1767.28,6154.58) 1790.08,6154.58 U39.6@1790.38,6154.88
CSI_B_CLOCK_N: CON11.8 CON18.28 | length 3262.9
  Top Layer w4: v1(4754.49,2886.33) 4760.89,2892.73 4772.89,2892.73 4778.39,2887.23 4790.39,2887.23 4795.89,2892.73 4807.89,2892.73 4813.39,2887.23 4825.39,2887.23 4830.89,2892.73 4842.89,2892.73 4848.39,2887.23 4860.39,2887.23 4865.89,2892.73 5160.22,2892.73 5262.8,2790.15 5262.8,2263.91 5907.18,1619.53 6188.18,1619.53 6439.25,1368.46 6856.47,1368.46 6861.56,1363.36 CON11.8@6887.83,1363.36 ; v1(4772.62,2811.03) 4778.72,2804.94 4778.72,2799.92 4773.62,2794.83 CON18.28@4773.62,2750.44
  Bottom Layer w4: v1(4754.49,2886.33) 4760.99,2892.84 4769.77,2892.84 4779.04,2883.56 4779.04,2817.45 v1(4772.62,2811.03)
CSI_B_CLOCK_P: CON11.9 CON18.26 | length 3264.3
  Top Layer w4: v1(4754.49,2908.15) 4760.4,2902.23 5164.16,2902.23 5272.3,2794.09 5272.3,2267.84 5911.11,1629.03 6192.11,1629.03 6443.19,1377.96 6856.5,1377.96 6861.6,1383.05 CON11.9@6887.83,1383.05 ; CON18.26@4793.31,2750.44 4793.31,2794.63 4788.22,2799.72 4788.22,2804.5 4794.44,2810.72 v1(4794.44,2811.03)
  Bottom Layer w4: v1(4754.49,2908.15) 4760.3,2902.34 4773.71,2902.34 4788.54,2887.5 4788.54,2816.93 v1(4794.44,2811.03)
CSI_B_DATA0_N: CON11.2 CON18.2 | length 3261.6
  Top Layer w4: CON18.2@5029.53,2750.44 5029.53,2796.39 5024.44,2801.48 5024.44,2812.29 5035.39,2823.24 5047.39,2823.24 5052.9,2817.74 5064.9,2817.74 5070.4,2823.24 5082.4,2823.24 5087.9,2817.74 5099.9,2817.74 5105.4,2823.24 5120.99,2823.24 5129.48,2814.76 5129.48,2806.98 5137.96,2798.49 5145.74,2798.5 5197.53,2746.71 5197.53,2208.39 5921.92,1483.99 6077.53,1483.99 6103.28,1458.24 6106.66,1454.86 6108.1,1453.42 ccw(c6121.49,1466.9) 6134.93,1453.47 cw(c6141.64,1446.75) 6148.36,1453.47 6257.72,1344.11 cw(c6251,1337.39) 6257.72,1330.67 cw(c6251,1337.39) 6244.28,1330.67 6164.72,1410.24 ccw(c6151.29,1396.8) 6137.87,1410.26 ; 6137.83,1410.21 ccw(c6151.29,1396.8) 6137.85,1383.37 6242.23,1278.99 ccw(c6255.63,1292.45) 6269.07,1279.02 cw(c6275.78,1272.3) 6282.52,1279 6287.27,1274.25 6311.17,1250.35 6857.49,1250.35 6862.58,1245.25 CON11.2@6887.83,1245.25
CSI_B_DATA0_P: CON11.3 CON18.4 | length 3263.7
  Top Layer w4: CON18.4@5009.84,2750.44 5009.84,2797.19 5014.94,2802.29 5014.94,2816.22 5031.46,2832.74 5124.93,2832.74 5207.03,2750.65 5207.03,2212.32 5925.86,1493.49 6081.46,1493.49 6110,1464.96 6113.38,1461.58 6114.8,1460.15 ccw(c6121.49,1466.9) 6128.21,1460.19 cw(c6141.64,1446.75) 6155.08,1460.18 6264.43,1350.83 cw(c6251,1337.39) 6264.43,1323.96 cw(c6251,1337.39) 6237.56,1323.96 6158,1403.52 ccw(c6151.29,1396.8) 6144.57,1403.52 ccw(c6151.29,1396.8) 6144.57,1390.08 6248.94,1285.72 ccw(c6255.63,1292.45) 6262.35,1285.74 cw(c6275.78,1272.3) 6289.22,1285.74 6293.99,1280.96 6315.11,1259.85 6856.98,1259.85 6862.07,1264.94 CON11.3@6887.83,1264.94
CSI_B_DATA1_N: CON11.5 CON18.8 | length 3261.2
  Top Layer w4: CON18.8@4970.47,2750.44 4970.47,2797.48 4965.95,2802 4965.95,2834.4 4991.44,2859.89 5003.44,2859.89 5008.94,2854.38 5020.94,2854.38 5026.44,2859.89 5038.44,2859.89 5043.94,2854.38 5055.94,2854.38 5061.44,2859.89 5073.44,2859.89 5078.94,2854.38 5090.94,2854.38 5096.44,2859.89 5143.27,2859.89 5230.85,2772.31 5230.85,2235.6 5895.93,1570.52 6138.49,1570.52 6157.47,1551.54 6162.23,1546.78 cw(c6155.5,1540.07) 6162.28,1546.73 ; 6162.29,1546.72 cw(c6155.52,1540.05) 6162.23,1533.32 ccw(c6175.68,1519.9) 6162.22,1506.48 6234.86,1433.84 ccw(c6248.3,1447.27) 6261.73,1433.84 ccw(c6248.3,1447.27) 6261.73,1460.71 6209.26,1513.18 cw(c6215.98,1519.9) 6222.7,1526.61 6295.88,1453.44 cw(c6289.14,1446.74) 6295.84,1440.01 ccw(c6309.29,1426.59) 6295.81,1413.2 6297.25,1411.76 6300.63,1408.38 6399.61,1309.4 6857.01,1309.4 6862.11,1304.31 CON11.5@6887.83,1304.31
CSI_B_DATA1_P: CON11.6 CON18.10 | length 3263.7
  Top Layer w4: CON18.10@4950.79,2750.44 4950.79,2797.85 4956.45,2803.51 4956.45,2838.33 4987.5,2869.39 5147.21,2869.39 5240.35,2776.25 5240.35,2239.53 5899.86,1580.02 6142.43,1580.02 6164.19,1558.26 6168.95,1553.49 cw(c6155.5,1540.07) 6169,1553.44 cw(c6155.52,1540.05) 6168.94,1526.59 ccw(c6175.68,1519.9) 6168.95,1513.19 6241.58,1440.56 ccw(c6248.3,1447.27) 6255.02,1440.56 ccw(c6248.3,1447.27) 6255.02,1453.99 6202.55,1506.46 cw(c6215.98,1519.9) 6229.42,1533.33 6302.6,1460.15 cw(c6289.14,1446.74) 6302.55,1433.29 ccw(c6309.29,1426.59) 6302.55,1419.9 6303.96,1418.48 6307.35,1415.1 6403.54,1318.9 6856.31,1318.9 6861.4,1323.99 CON11.6@6887.83,1323.99
CSI_B_DATA2_N: CON11.11 CON18.22 | length 3261.8
  Top Layer w4: v1(4816.37,2920.72) 4822.51,2926.86 4834.51,2926.86 4840.01,2921.36 4852.01,2921.36 4857.51,2926.86 4869.51,2926.86 4875.02,2921.36 4887.02,2921.36 4892.52,2926.86 4904.52,2926.86 4910.02,2921.36 4922.02,2921.36 4927.52,2926.86 5173.75,2926.86 5292.88,2807.74 5292.88,2289.37 5456.08,2126.17 5515.1,2126.17 5964.88,1676.39 6215.8,1676.39 6378.69,1513.5 6383.45,1508.74 ccw(c6396.9,1522.16) 6410.34,1508.72 6414.32,1512.7 cw(c6421.03,1505.99) 6427.75,1512.7 cw(c6421.03,1505.99) 6427.75,1499.27 6423.77,1495.29 ccw(c6437.21,1481.85) 6423.79,1468.4 6446.44,1445.75 6464.67,1427.51 6854.57,1427.51 6859.66,1422.42 CON11.11@6887.83,1422.42 ; v1(4831.51,2843.55) 4837.77,2837.29 4837.77,2804.21 4832.68,2799.12 CON18.22@4832.68,2750.44
  Bottom Layer w4: v1(4816.37,2920.72) 4822.63,2926.98 4830.54,2926.98 4837.67,2919.84 4837.67,2849.71 v1(4831.51,2843.55)
CSI_B_DATA2_P: CON11.12 CON18.20 | length 3263.7
  Top Layer w4: v1(4816.37,2942.54) 4822.55,2936.36 5177.69,2936.36 5302.38,2811.67 5302.38,2293.31 5460.01,2135.67 5519.03,2135.67 5968.81,1685.89 6219.73,1685.89 6385.41,1520.21 6390.18,1515.44 ccw(c6396.9,1522.16) 6403.62,1515.44 6407.6,1519.42 cw(c6421.03,1505.99) 6434.47,1519.42 cw(c6421.03,1505.99) 6434.47,1492.55 6430.49,1488.57 ccw(c6437.21,1481.85) 6430.49,1475.13 6453.16,1452.46 6468.61,1437.01 6855.88,1437.01 6860.97,1442.11 CON11.12@6887.83,1442.11 ; CON18.20@4852.36,2750.44 4852.36,2798.45 4847.27,2803.54 4847.27,2837.49 v1(4853.33,2843.55)
  Bottom Layer w4: v1(4816.37,2942.54) 4822.43,2936.48 4834.48,2936.48 4847.17,2923.78 4847.17,2849.71 v1(4853.33,2843.55)
CSI_B_DATA3_N: CON11.14 CON18.16 | length 3261.6
  Top Layer w4: v1(4873.09,2957.81) 4878.98,2963.7 4890.98,2963.7 4896.48,2958.2 4908.48,2958.2 4913.99,2963.7 4925.99,2963.7 4931.49,2958.2 4943.49,2958.2 4948.99,2963.7 4960.99,2963.7 4966.49,2958.2 4978.49,2958.2 4983.99,2963.7 5185.09,2963.7 5334.79,2814.01 5334.79,2293.36 5442.92,2185.23 5547.83,2185.23 6001.33,1731.73 6260.97,1731.73 6338.53,1654.17 6343.29,1649.41 ccw(c6356.74,1662.83) 6370.18,1649.4 6382.78,1662 cw(c6389.5,1655.28) 6396.22,1662 cw(c6389.5,1655.28) 6396.22,1648.57 6383.61,1635.96 ccw(c6397.05,1622.53) 6383.63,1609.08 6422.85,1569.85 6453.6,1539.1 6530.41,1539.1 6582.94,1486.57 6856.66,1486.57 6861.75,1481.48 CON11.14@6887.83,1481.48 ; v1(4890.73,2812.51) 4896.63,2806.6 4896.63,2799.65 4891.73,2794.75 CON18.16@4891.73,2750.44
  Bottom Layer w4: v1(4873.09,2957.81) 4879.16,2963.88 4890.91,2963.88 4897.24,2957.54 4897.24,2819.03 v1(4890.73,2812.51)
